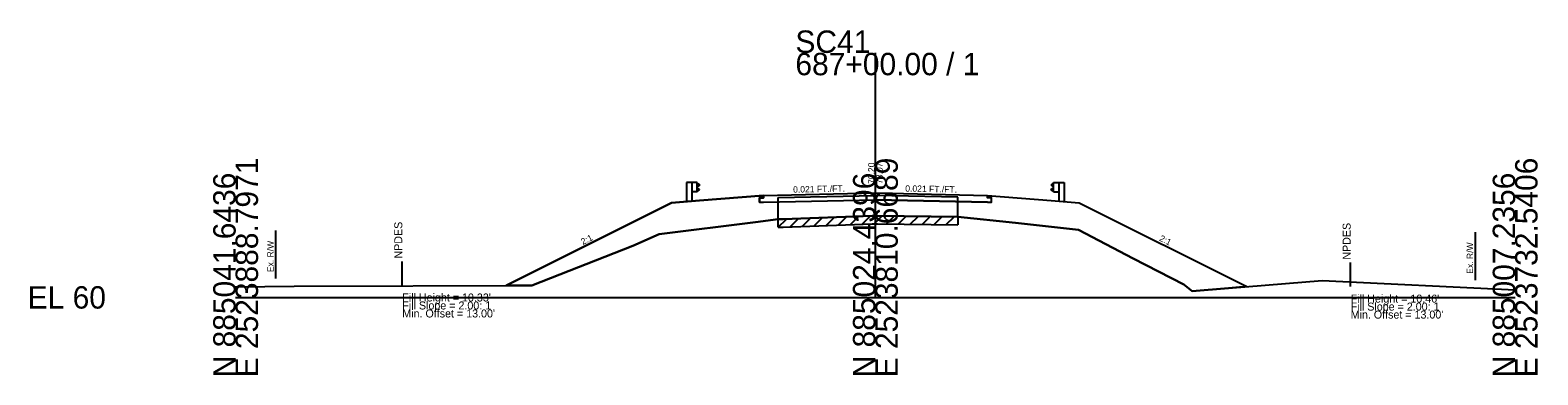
# Model space of a CAD drawing. Extents: x -26 to 183, y -10 to 24021.
# Drawn here: x -25.7 to 162.8, y 15490.3 to 15533.4 of the extents above; entities that cross this region are included whole.
import ezdxf

# ---------------------------------------------------------------- set-up
doc = ezdxf.new("R2010")
doc.units = 0
for name, color, linetype in [('RD_GPK_XS_Cell', 7, 'Continuous'), ('RD_XS_Base', 7, 'Continuous'), ('RD_XS_Buildup', 7, 'Continuous'), ('RD_XS_EarthShd', 7, 'Continuous'), ('RD_XS_EwShp', 7, 'Continuous'), ('RD_XS_ExGround', 7, 'Continuous'), ('RD_XS_ExPaveRet', 7, 'Continuous'), ('RD_XS_ExRW', 7, 'Continuous'), ('RD_XS_GR', 7, 'Continuous'), ('RD_XS_NPDES', 7, 'Continuous'), ('RD_XS_Pave', 7, 'Continuous'), ('RD_XS_TieSlope', 7, 'Continuous'), ('RD_XS_TX_Elev_EX', 7, 'Continuous'), ('RD_XS_TX_Elev_PR', 7, 'Continuous'), ('RD_XS_TX_Slope', 7, 'Continuous'), ('RD_XS_TX_Warning', 7, 'Continuous')]:
    doc.layers.add(name, color=color, linetype=linetype)

msp = doc.modelspace()

# ---------------------------------------------------------------- linework, layer by layer
at = {"layer": 'RD_GPK_XS_Cell'}
for p, q in [((80, 15500), (80, 15530.6)), ((0, 15500), (80, 15500)), ((80, 15500), (160, 15500))]:
    msp.add_line(p, q, dxfattribs=at)
at = {"layer": 'RD_XS_Base'}
for p in [(66.01, 15511.93), (94.01, 15511.93)]:
    msp.add_line(p, (80.01, 15512.23), dxfattribs=at)
at = {"layer": 'RD_XS_Buildup'}
for p, q in [((67.86, 15512.49), (80, 15512.75)), ((67.86, 15509.78), (67.86, 15512.49)), ((90.33, 15512.53), (80, 15512.75)), ((90.33, 15510.09), (90.33, 15512.53))]:
    msp.add_line(p, q, dxfattribs=at)
at = {"layer": 'RD_XS_EarthShd'}
for p, q in [((66, 15512.77), (58, 15512.11)), ((94, 15512.77), (102, 15512.11)), ((58, 15512.11), (54.5, 15511.82)), ((102, 15512.11), (105.5, 15511.82))]:
    msp.add_line(p, q, dxfattribs=at)
at = {"layer": 'RD_XS_EwShp'}
for points in [[(65.5, 15511.92), (66.01, 15511.93), (80.01, 15512.23), (94.01, 15511.93), (94.5, 15511.92), (94.5, 15512.47), (94, 15512.48), (94, 15512.77), (102, 15512.11), (105.5, 15511.82), (126.43, 15501.35), (124.15, 15501.17), (119.62, 15500.8), (118.58, 15501.6), (112.22, 15504.87), (105.38, 15508.46), (97.51, 15509.33), (90.33, 15510.09), (80.25, 15510.2), (79.61, 15510.2), (68.46, 15509.8), (67.86, 15509.78), (64.99, 15509.42), (52.98, 15507.92), (49.69, 15506.44), (37.02, 15501.5), (33.84, 15501.49), (54.5, 15511.82), (58, 15512.11), (66, 15512.77), (66, 15512.48), (65.5, 15512.47)], [(102, 15512.11), (105.5, 15511.82), (126.43, 15501.35), (124.15, 15501.17), (119.62, 15500.8), (118.58, 15501.6), (112.22, 15504.87), (105.38, 15508.46), (97.51, 15509.33), (90.33, 15510.09), (80.25, 15510.2), (79.61, 15510.2), (68.46, 15509.8), (67.86, 15509.78), (64.99, 15509.42), (52.98, 15507.92), (49.69, 15506.44), (37.02, 15501.5), (33.84, 15501.49), (54.5, 15511.82), (58, 15512.11), (66, 15512.77), (66, 15512.48), (65.5, 15512.47), (65.5, 15511.92), (66.01, 15511.93), (80.01, 15512.23), (94.01, 15511.93), (94.5, 15511.92), (94.5, 15512.47), (94, 15512.48), (94, 15512.77)], [(102, 15512.11), (105.5, 15511.82), (126.43, 15501.35), (124.15, 15501.17), (119.62, 15500.8), (118.58, 15501.6), (112.22, 15504.87), (105.38, 15508.46), (97.51, 15509.33), (90.33, 15510.09), (80.25, 15510.2), (79.61, 15510.2), (68.46, 15509.8), (67.86, 15509.78), (64.99, 15509.42), (52.98, 15507.92), (49.69, 15506.44), (37.02, 15501.5), (33.84, 15501.49), (54.5, 15511.82), (58, 15512.11), (66, 15512.77), (66, 15512.48), (65.5, 15512.47), (65.5, 15511.92), (66.01, 15511.93), (80.01, 15512.23), (94.01, 15511.93), (94.5, 15511.92), (94.5, 15512.47), (94, 15512.48), (94, 15512.77)], [(102, 15512.11), (105.5, 15511.82), (126.43, 15501.35), (124.15, 15501.17), (119.62, 15500.8), (118.58, 15501.6), (112.22, 15504.87), (105.38, 15508.46), (97.51, 15509.33), (90.33, 15510.09), (80.25, 15510.2), (79.61, 15510.2), (68.46, 15509.8), (67.86, 15509.78), (64.99, 15509.42), (52.98, 15507.92), (49.69, 15506.44), (37.02, 15501.5), (33.84, 15501.49), (54.5, 15511.82), (58, 15512.11), (66, 15512.77), (66, 15512.48), (65.5, 15512.47), (65.5, 15511.92), (66.01, 15511.93), (80.01, 15512.23), (94.01, 15511.93), (94.5, 15511.92), (94.5, 15512.47), (94, 15512.48), (94, 15512.77)]]:
    msp.add_lwpolyline(points, close=True, dxfattribs=at)
at = {"layer": 'RD_XS_ExGround'}
for p, q in [((52.98, 15507.92), (64.99, 15509.42)), ((64.99, 15509.42), (67.86, 15509.78)), ((67.86, 15509.78), (68.46, 15509.8)), ((68.46, 15509.8), (79.61, 15510.2)), ((79.61, 15510.2), (80.25, 15510.2)), ((80.25, 15510.2), (90.33, 15510.09)), ((90.33, 15510.09), (97.51, 15509.33)), ((97.51, 15509.33), (105.38, 15508.46)), ((49.69, 15506.44), (52.98, 15507.92)), ((105.38, 15508.46), (112.22, 15504.87)), ((37.02, 15501.5), (49.69, 15506.44)), ((112.22, 15504.87), (118.58, 15501.6)), ((0, 15501.33), (7.32, 15501.39)), ((7.32, 15501.39), (37.02, 15501.5)), ((118.58, 15501.6), (119.62, 15500.8)), ((119.62, 15500.8), (124.15, 15501.17)), ((124.15, 15501.17), (135.88, 15502.12)), ((135.88, 15502.12), (160, 15500.93))]:
    msp.add_line(p, q, dxfattribs=at)
at = {"layer": 'RD_XS_ExPaveRet'}
for p, q in [((67.86, 15508.78), (68.9, 15509.81)), ((67.86, 15508.78), (67.86, 15509.78)), ((67.86, 15508.78), (68.46, 15508.8)), ((68.46, 15508.8), (79.61, 15509.2)), ((69.36, 15508.83), (70.4, 15509.87)), ((70.86, 15508.88), (71.9, 15509.92)), ((72.36, 15508.94), (73.4, 15509.98)), ((73.86, 15508.99), (74.9, 15510.03)), ((75.36, 15509.05), (76.4, 15510.08)), ((76.86, 15509.1), (77.9, 15510.14)), ((78.36, 15509.16), (79.4, 15510.19)), ((79.61, 15509.2), (80.25, 15509.2)), ((79.86, 15509.2), (80.85, 15510.19)), ((80.25, 15509.2), (90.33, 15509.09)), ((81.36, 15509.18), (82.35, 15510.17)), ((82.86, 15509.17), (83.85, 15510.16)), ((84.36, 15509.15), (85.35, 15510.14)), ((85.86, 15509.14), (86.85, 15510.13)), ((87.36, 15509.12), (88.35, 15510.11)), ((88.86, 15509.11), (89.85, 15510.1)), ((90.33, 15510.09), (90.33, 15509.09))]:
    msp.add_line(p, q, dxfattribs=at)
at = {"layer": 'RD_XS_ExRW'}
for p, q in [((5, 15508.37), (5, 15502.37)), ((155, 15508.17), (155, 15502.17))]:
    msp.add_line(p, q, dxfattribs=at)
at = {"layer": 'RD_XS_GR'}
for p, q in [((56.4, 15514.36), (56.4, 15511.97)), ((57.06, 15514.36), (56.4, 15514.36)), ((57.06, 15514.36), (57.06, 15512.03)), ((57.73, 15514.36), (57.06, 15514.36)), ((57.73, 15513.19), (57.73, 15514.36)), ((102.27, 15513.19), (102.27, 15514.36)), ((102.27, 15514.36), (102.94, 15514.36)), ((102.94, 15514.36), (102.94, 15512.03)), ((102.94, 15514.36), (103.6, 15514.36)), ((103.6, 15514.36), (103.6, 15511.97)), ((57.73, 15513.19), (57.06, 15513.19)), ((57.73, 15514.28), (58, 15514.08)), ((58, 15514.03), (57.73, 15513.83)), ((58, 15513.51), (57.73, 15513.71)), ((57.73, 15513.26), (58, 15513.46)), ((58, 15514.08), (58, 15514.03)), ((58, 15513.46), (58, 15513.51)), ((102.27, 15514.28), (102, 15514.08)), ((102, 15514.08), (102, 15514.03)), ((102, 15514.03), (102.27, 15513.83)), ((102, 15513.51), (102.27, 15513.71)), ((102, 15513.46), (102, 15513.51)), ((102.27, 15513.26), (102, 15513.46)), ((102.27, 15513.19), (102.94, 15513.19))]:
    msp.add_line(p, q, dxfattribs=at)
at = {"layer": 'RD_XS_NPDES'}
for p, q in [((20.84, 15501.49), (20.84, 15504.49)), ((139.43, 15501.35), (139.43, 15504.35))]:
    msp.add_line(p, q, dxfattribs=at)
at = {"layer": 'RD_XS_Pave'}
for p, q in [((65.5, 15512.47), (66, 15512.48)), ((65.5, 15511.92), (65.5, 15512.47)), ((66, 15512.77), (80, 15513.07)), ((66, 15512.48), (66, 15512.77)), ((80, 15513.07), (94, 15512.77)), ((94, 15512.48), (94, 15512.77)), ((94.5, 15512.47), (94, 15512.48)), ((94.5, 15511.92), (94.5, 15512.47)), ((65.5, 15511.92), (66.01, 15511.93)), ((94.01, 15511.93), (94.5, 15511.92))]:
    msp.add_line(p, q, dxfattribs=at)
at = {"layer": 'RD_XS_TieSlope'}
for p, q in [((54.5, 15511.82), (33.84, 15501.49)), ((105.5, 15511.82), (126.43, 15501.35))]:
    msp.add_line(p, q, dxfattribs=at)

# ---------------------------------------------------------------- texts
at = {"layer": 'RD_GPK_XS_Cell'}
for s, p in [('SC41', (70, 15530.6)), ('687+00.00 / 1', (70, 15527.8)), ('EL 60', (-26, 15498.6))]:
    msp.add_text(s, height=2.8, dxfattribs=at).set_placement(p)
for s, p in [('E 2523888.7971', (2.8, 15490)), ('E 2523810.6689', (82.8, 15490)), ('E 2523732.5406', (162.8, 15490)), ('N 885041.6436', (0, 15490)), ('N 885024.4396', (80, 15490)), ('N 885007.2356', (160, 15490))]:
    msp.add_text(s, height=2.8, rotation=90, dxfattribs=at).set_placement(p)
at = {"layer": 'RD_XS_ExRW'}
for p in [(4.75, 15503.16), (154.75, 15502.96)]:
    msp.add_text('Ex. R/W ', height=0.8, rotation=90, dxfattribs=at).set_placement(p)
at = {"layer": 'RD_XS_TX_Elev_EX'}
msp.add_text('70.20', height=0.8, rotation=90, dxfattribs=at).set_placement((79.9, 15514.2))
at = {"layer": 'RD_XS_TX_Elev_PR'}
msp.add_text('73.07', height=0.8, rotation=90, dxfattribs=at).set_placement((80.9, 15514.2))
at = {"layer": 'RD_XS_TX_Slope'}
for s, rotation, p in [('0.021 FT./FT.', 1.1916, (69.72, 15513.1)), ('0.021 FT./FT.', 358.8084, (83.73, 15513.24)), ('2:1', 26.5651, (43.42, 15506.55)), ('2:1', 333.4349, (115.43, 15507.13))]:
    msp.add_text(s, height=0.8, rotation=rotation, dxfattribs=at).set_placement(p)
at = {"layer": 'RD_XS_TX_Warning'}
for p in [(20.84, 15504.49), (139.43, 15504.35)]:
    msp.add_text(' NPDES', height=1, rotation=90, dxfattribs=at).set_placement(p)
for s, p in [("Fill Height = 10.33' ", (20.84, 15499.49)), ('Fill Slope = 2.00: 1', (20.84, 15498.49)), ("Fill Height = 10.46' ", (139.43, 15499.35)), ('Fill Slope = 2.00: 1', (139.43, 15498.35)), ("Min. Offset = 13.00' ", (20.84, 15497.49)), ("Min. Offset = 13.00' ", (139.43, 15497.35))]:
    msp.add_text(s, height=1, dxfattribs=at).set_placement(p)

doc.saveas('drawing.dxf')
